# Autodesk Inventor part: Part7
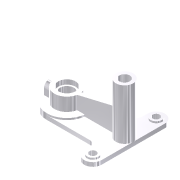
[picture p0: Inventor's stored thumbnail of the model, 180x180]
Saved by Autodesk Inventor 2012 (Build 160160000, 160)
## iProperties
Shininess: 77.0
Length Units: 11269
Angle Units: 11279
Time Units: 11290
Mass Units: 11283
Length Display Precision: 3
Angle Display Precision: 2
Created: 2001-12
Part Number: Part7
Document SubType Name: Modeling
Density: 1 g/cm^3
Material: Default
Density: 0.0
Volumn: 0.0
Area: 0.0
PropertySet Name: Model Information
Control State: 0
Master: False
Checked Out: False
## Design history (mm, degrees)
sketch "Sketch1"
  geometry: L1 (46.121, -53.4)-(46.121, 56.6); L2 (16.121, 56.6)-(16.121, 36.6); L3 (16.121, 36.6)-(-68.879, 36.6); L4 (-68.879, -33.4)-(16.121, -33.4); L5 (16.121, -33.4)-(16.121, -53.4); A1 r 15 centre (31.121, 56.6) between (46.121, 56.6) and (16.121, 56.6); A2 r 35 centre (-68.879, 1.6) between (-68.879, 36.6) and (-68.879, -33.4); A3 r 15 centre (31.121, -53.4) between (16.121, -53.4) and (46.121, -53.4)
  constraints: 10 end point, 6 point on circle, 5 tangent, 3 centre point, 3 parallel, 2 equal length, 1 equal radius, 1 perpendicular, 1 vertical
  dimensions: "d0" = 15 radius of A1; "d1" = 110 distance of L1.start L1.end; "d2" = 100 horizontal distance of A3.centre A2.centre; "d3" = 35 radius of A2
extrude "Extrusion1" new body sketch "Sketch1" distance "d4" = 7; taper "d5" = 0 deg
sketch "Sketch2"
  geometry: C1 r 10 at (31.121, 56.6); C2 r 10 at (31.121, -53.4); C3 r 35 at (-68.879, 1.6); A1 r 35 centre (-68.879, 1.6) between (-68.879, 36.6) and (-68.879, -33.4) reference; A2 r 15 centre (31.121, 56.6) between (46.121, 56.6) and (16.121, 56.6) reference; A3 r 15 centre (31.121, -53.4) between (16.121, -53.4) and (46.121, -53.4) reference
  constraints: 3 centre point, 3 concentric, 2 equal radius
  dimensions: "d45" = 20 diameter of C1
extrude "Extrusion2" join sketch "Sketch2" distance "d6" = 3; taper "d7" = 0 deg
sketch "Sketch3"
  geometry: C1 r 22 at (0, 0); 1 further point
  constraints: 1 centre point, 1 coincident
  dimensions: "d8" = 44 diameter of C1
extrude "Extrusion3" join sketch "Sketch3" distance "d9" = 23; taper "d10" = 0 deg
sketch "Sketch4"
  geometry: L1 (46.121, 56.6)-(46.121, -53.4) reference; L2 (-68.879, 36.6)-(16.121, 36.6) reference; C1 r 15 at (31.121, 1.6)
  constraints: 1 centre point
  dimensions: "d11" = 30 diameter of C1; "d12" = 15 distance from line of L1 C1.centre; "d13" = 35 distance from line of L2 C1.centre
extrude "Extrusion4" join sketch "Sketch4" distance "d14" = 88; taper "d15" = 0 deg
workplane "Work Plane1"
sketch "Sketch5"
  geometry: L1 (22, 33.1)-(85, 48); L2 (0, 7)-(35, 7) reference; L3 (85, 0)-(85, 7) reference; L4 (115, 0)-(115, 7) reference; L5 (115, 0)-(85, 0) reference
  constraints: 2 end point
  dimensions: "d17" = 26.1 distance from line of L2 L1.start; "d18" = 63 distance from line of L3 L1.start; "d19" = 30 distance from line of L4 L1.end; "d20" = 48 distance from line of L5 L1.end
feature "Rib1" sketch "Sketch5" dims "d21" = 1, "d22" = 8
workplane "Work Plane2"
workplane "Work Plane3"
sketch "Sketch7"
  geometry: L1 (10, 0)-(10, 10); L2 (-10, 10)-(-10, 0); L3 (-10, 0)-(10, 0); L4 (55, -10)-(55, -3) reference; A1 r 10 centre (0, 10) between (10, 10) and (-10, 10); 2 further points
  constraints: 6 end point, 2 point on circle, 2 tangent, 1 centre point, 1 parallel, 1 perpendicular, 1 vertical
  dimensions: "d30" = 10 radius of A1; "d34" = 55 distance from line of L4 A1.centre; "d35" = 10 distance of L1.start L1.end
extrude "Extrusion6" join sketch "Sketch7" stored distance "d36" = 88; taper "d37" = 0 deg
sketch "Sketch8"
  geometry: C1 r 10 at (0, 0) reference
hole "Hole1" sketch "Sketch8" at (0, 0) diameter "d38" = 12; stored, may be unused: countersink angle "d42" = 82 deg, drill point angle "d44" = 118 deg; dims "d39" = 6, "d40" = 4, "d41" = 2, "d43" = 8
mirror "Mirror1"
sketch "Sketch9"
  geometry: C1 r 10 at (0, 0)
  constraints: 1 centre point
hole "Hole2" sketch "Sketch9" at (0, 0) diameter "d52" = 18; stored, may be unused: drill point angle "d47" = 118 deg, countersink angle "d48" = 82 deg; dims "d46" = 6, "d49" = 2, "d50" = 4, "d51" = 8
sketch "Sketch10"
  geometry: C1 r 10 at (0, 0)
  constraints: 1 centre point
hole "Hole3" sketch "Sketch10" at (0, 0) diameter "d59" = 24; stored, may be unused: drill point angle "d54" = 118 deg, countersink angle "d55" = 82 deg; dims "d53" = 6, "d56" = 8, "d57" = 30, "d58" = 8
sketch "Sketch11"
  geometry: C1 r 10 at (0, 0)
  constraints: 1 centre point
hole "Hole4" sketch "Sketch11" at (0, 0) diameter "d66" = 10; stored, may be unused: drill point angle "d61" = 0 deg, countersink angle "d62" = 82 deg; dims "d60" = 6, "d63" = 2, "d64" = 4, "d65" = 8
fillet "Fillet1" dims "d67" = 10
body "Solid1"
other parameters: "d16" = -35, "d29" = -8
